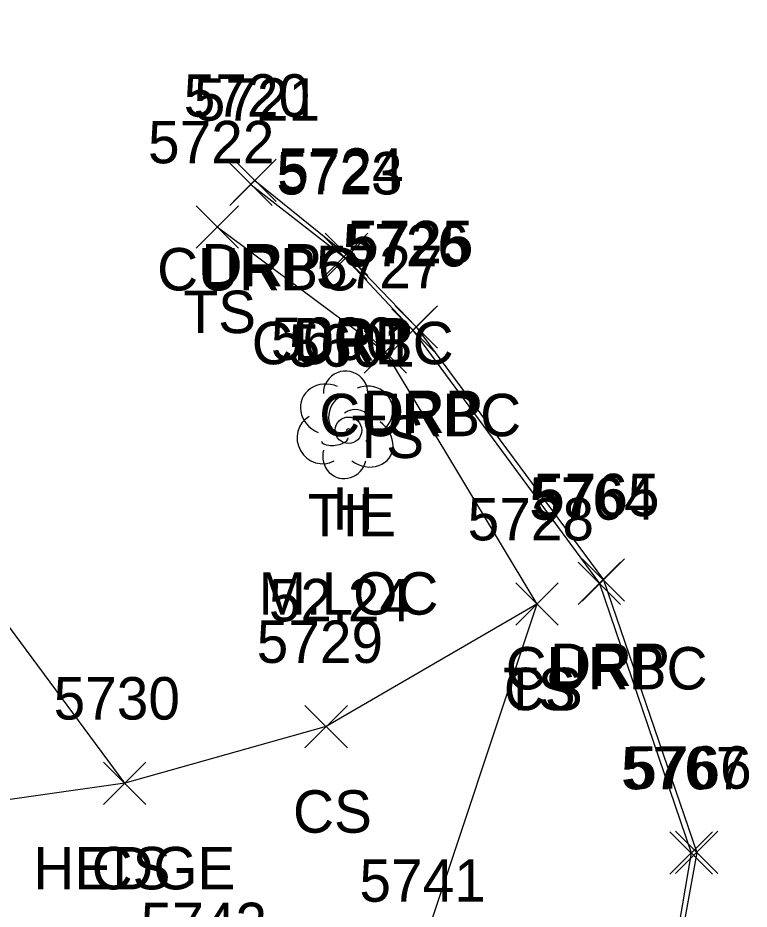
# Model space of a CAD drawing. Extents: x 1505656 to 1508446, y 700805 to 703031.
# Drawn here: x 1508219.01 to 1508253.45, y 701002.58 to 701044.57 of the extents above; entities that cross this region are included whole.
import ezdxf

# ---------------------------------------------------------------- set-up
doc = ezdxf.new("R2010")
doc.units = 0
for name, color, linetype in [('C_A', 7, 'Continuous'), ('C_C', 7, 'Continuous'), ('C_I', 7, 'Continuous'), ('CBP', 7, 'Continuous'), ('L_A', 7, 'Continuous'), ('L_C', 7, 'Continuous'), ('L_I', 7, 'Continuous'), ('L_TIC', 7, 'Continuous'), ('LAHR', 7, 'Continuous'), ('LELB', 7, 'Continuous'), ('LTD', 7, 'Continuous'), ('R_A', 7, 'Continuous'), ('R_I', 7, 'Continuous'), ('R_TIC', 7, 'Continuous'), ('RC', 7, 'Continuous'), ('RDP', 7, 'Continuous')]:
    doc.layers.add(name, color=color, linetype=linetype)

msp = doc.modelspace()

# ---------------------------------------------------------------- linework, layer by layer
at = {"layer": 'CBP'}
for radius in [0.625, 0.0833]:
    msp.add_circle((1508234.582, 701025.141), radius, dxfattribs=at)
at = {"layer": 'L_TIC'}
for points in [[(1508227.404, 701033.721), (1508229.404, 701035.721)], [(1508229.404, 701033.721), (1508227.404, 701035.721)], [(1508235.316, 701027.834), (1508237.316, 701029.834)], [(1508237.316, 701027.834), (1508235.316, 701029.834)], [(1508242.457, 701015.955), (1508244.457, 701017.955)], [(1508244.457, 701015.955), (1508242.457, 701017.955)], [(1508242.457, 701015.955), (1508244.457, 701017.955)], [(1508244.457, 701015.955), (1508242.457, 701017.955)], [(1508232.531, 701010.182), (1508234.531, 701012.182)], [(1508234.531, 701010.182), (1508232.531, 701012.182)], [(1508223.046, 701007.513), (1508225.046, 701009.513)], [(1508225.046, 701007.513), (1508223.046, 701009.513)], [(1508223.046, 701007.513), (1508225.046, 701009.513)], [(1508225.046, 701007.513), (1508223.046, 701009.513)]]:
    msp.add_lwpolyline(points, dxfattribs=at)
at = {"layer": 'LAHR'}
msp.add_lwpolyline([(1508224.046, 701008.513), (1508210.992, 701026.162)], dxfattribs=at)
at = {"layer": 'LELB'}
for points in [[(1508228.404, 701034.721), (1508236.316, 701028.834), (1508243.457, 701016.955), (1508237.793, 700999.931), (1508220.382, 700978.225), (1508211.627, 700976.182), (1508200.235, 700981.483), (1508176.077, 700993.302), (1508134.871, 701022.609), (1508102.046, 701043.729), (1508059.544, 701072.446), (1508045.58, 701083.254), (1508024.829, 701096.462), (1507993.796, 701118.004), (1507968.478, 701136.482), (1507954.541, 701151.103), (1507949.818, 701167.812), (1507943.91, 701185.442), (1507939.542, 701206.063), (1507946.418, 701227.54), (1507956.393, 701251.264), (1507981.337, 701275.267), (1508009.303, 701301.946), (1508033.182, 701318.193)], [(1508243.457, 701016.955), (1508233.531, 701011.182), (1508224.046, 701008.513), (1508207.387, 701006.148), (1508193.012, 701021.757), (1508177.933, 701039.568), (1508161.215, 701059.009), (1508156.325, 701086.224), (1508157.553, 701097.744), (1508166.281, 701116.032), (1508176.03, 701129.466)]]:
    msp.add_lwpolyline(points, dxfattribs=at)
at = {"layer": 'LTD'}
msp.add_line((1508234.404, 701025.455), (1508234.404, 701025.455), dxfattribs=at)
msp.add_line((1508234.404, 701025.455), (1508234.404, 701025.455), dxfattribs=at)
msp.add_arc((1508234.45, 701026.889), 1.047, 335.5272, 180.9563, dxfattribs=at)
for centre, major_axis, ratio, start_param, end_param in [((1508233.612, 701026.122), (1.21, -0.512), 0.895232, 1.570796, 4.712389), ((1508235.445, 701026.039), (-1.141, -0.483), 0.949671, 1.570796, 4.712389), ((1508234.195, 701025.914), (-0.208, -0.792), 0.645439, 3.141593, 6.283185), ((1508234.904, 701025.289), (-0.5, 0.667), 0.989748, 3.141593, 6.283185), ((1508233.32, 701024.747), (0.584, -1.042), 0.959034, 3.141593, 6.283185), ((1508235.404, 701024.622), (-1.09, 0.792), 0.841452, 1.570796, 4.712389), ((1508233.945, 701024.705), (-0.625, -0.083), 0.423636, 0, 3.141593), ((1508234.404, 701023.955), (0.265, 1.061), 0.942809, 1.570796, 4.712389)]:
    msp.add_ellipse(centre, major_axis=major_axis, ratio=ratio, start_param=start_param, end_param=end_param, dxfattribs=at)
at = {"layer": 'R_TIC'}
for points in [[(1508228.99, 701035.73), (1508230.99, 701037.73)], [(1508230.99, 701035.73), (1508228.99, 701037.73)], [(1508229.173, 701035.917), (1508231.173, 701037.917)], [(1508231.173, 701035.917), (1508229.173, 701037.917)], [(1508233.494, 701032.428), (1508235.494, 701034.428)], [(1508235.494, 701032.428), (1508233.494, 701034.428)], [(1508233.445, 701032.253), (1508235.445, 701034.253)], [(1508235.445, 701032.253), (1508233.445, 701034.253)], [(1508236.776, 701029.011), (1508238.776, 701031.011)], [(1508238.776, 701029.011), (1508236.776, 701031.011)], [(1508236.622, 701028.861), (1508238.622, 701030.861)], [(1508238.622, 701028.861), (1508236.622, 701030.861)], [(1508245.4, 701016.93), (1508247.4, 701018.93)], [(1508247.4, 701016.93), (1508245.4, 701018.93)], [(1508245.586, 701017.093), (1508247.586, 701019.093)], [(1508247.586, 701017.093), (1508245.586, 701019.093)], [(1508249.723, 701004.227), (1508251.723, 701006.227)], [(1508251.723, 701004.227), (1508249.723, 701006.227)], [(1508249.982, 701004.256), (1508251.982, 701006.256)], [(1508251.982, 701004.256), (1508249.982, 701006.256)]]:
    msp.add_lwpolyline(points, dxfattribs=at)
at = {"layer": 'RC'}
msp.add_lwpolyline([(1508229.99, 701036.73), (1508234.445, 701033.253), (1508237.622, 701029.861), (1508246.4, 701017.93), (1508250.723, 701005.227), (1508249.206, 700996.269), (1508246.47, 700991.497), (1508245.12, 700989.161), (1508243.536, 700987.162), (1508239.965, 700981.944), (1508235.891, 700976.958), (1508231.197, 700973.39), (1508226.416, 700970.881), (1508220.352, 700969.176), (1508215.713, 700968.836), (1508214.535, 700968.679)], dxfattribs=at)
at = {"layer": 'RDP'}
msp.add_lwpolyline([(1508230.173, 701036.917), (1508234.494, 701033.428), (1508237.776, 701030.011), (1508246.586, 701018.093), (1508250.982, 701005.256), (1508249.339, 700996.184), (1508246.748, 700991.497)], dxfattribs=at)

# ---------------------------------------------------------------- texts
at = {"layer": 'C_A'}
msp.add_text('TIE', height=2, dxfattribs=at).set_placement((1508232.661, 701020.141))
at = {"layer": 'C_C'}
msp.add_text('52.24', height=2, dxfattribs=at).set_placement((1508230.834, 701016.141))
at = {"layer": 'C_I'}
msp.add_text('5601', height=2, dxfattribs=at).set_placement((1508231.763, 701028.141))
at = {"layer": 'L_A'}
for s, p in [('TS', (1508226.813, 701029.721)), ('TS', (1508234.726, 701023.834)), ('H', (1508233.837, 701020.455)), ('TS', (1508241.866, 701011.955)), ('CS', (1508241.898, 701011.955)), ('CS', (1508231.972, 701006.182)), ('HEDGE', (1508219.747, 701003.513)), ('CS', (1508222.487, 701003.513))]:
    msp.add_text(s, height=2, dxfattribs=at).set_placement(p)
at = {"layer": 'L_C'}
msp.add_text('M.LOC', height=2, dxfattribs=at).set_placement((1508230.348, 701016.455))
at = {"layer": 'L_I'}
for s, p in [('5722', (1508225.144, 701037.721)), ('5727', (1508233.056, 701031.834)), ('5600', (1508230.931, 701028.455)), ('5728', (1508240.197, 701019.955)), ('5728', (1508240.197, 701019.955)), ('5729', (1508230.263, 701014.182)), ('5730', (1508220.699, 701011.513)), ('5730', (1508220.699, 701011.513)), ('5741', (1508235.1, 701002.931)), ('5741', (1508235.1, 701002.931)), ('5742', (1508224.797, 701000.886))]:
    msp.add_text(s, height=2, dxfattribs=at).set_placement(p)
at = {"layer": 'R_A'}
for s, p in [('DRP', (1508227.661, 701031.917)), ('CURBC', (1508225.572, 701031.73)), ('CURBC', (1508230.028, 701028.253)), ('DRP', (1508231.982, 701028.428)), ('CURBC', (1508233.205, 701024.861)), ('DRP', (1508235.265, 701025.011)), ('DRP', (1508244.074, 701013.093)), ('CURBC', (1508241.983, 701012.93))]:
    msp.add_text(s, height=2, dxfattribs=at).set_placement(p)
at = {"layer": 'R_I'}
for s, p in [('5720', (1508226.826, 701039.917)), ('5721', (1508227.297, 701039.73)), ('5723', (1508231.185, 701036.253)), ('5724', (1508231.234, 701036.428)), ('5726', (1508234.307, 701032.861)), ('5725', (1508234.517, 701033.011)), ('5765', (1508243.279, 701021.093)), ('5764', (1508243.093, 701020.93)), ('5767', (1508247.416, 701008.227)), ('5766', (1508247.62, 701008.256))]:
    msp.add_text(s, height=2, dxfattribs=at).set_placement(p)

doc.saveas('drawing.dxf')
